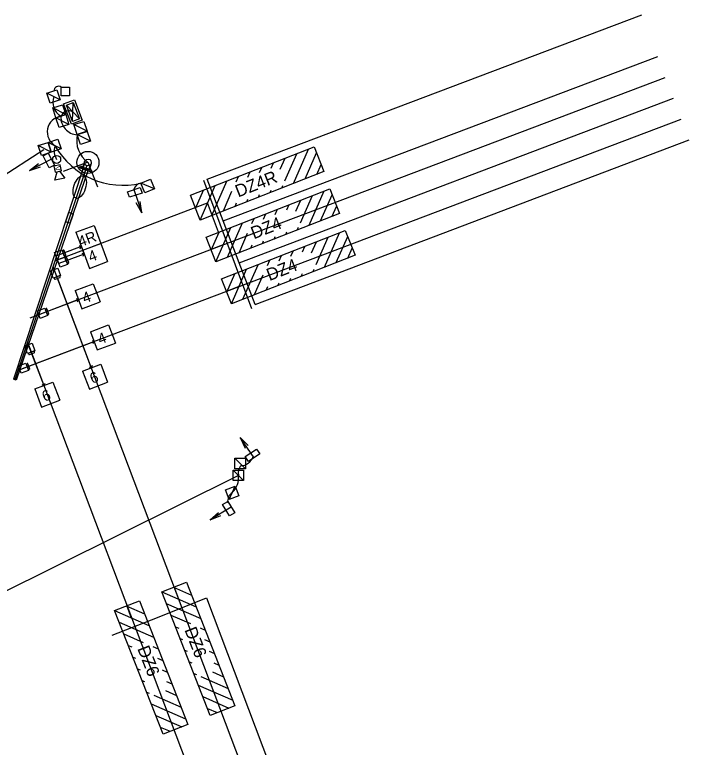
# Model space of a CAD drawing. Extents: x 510435 to 510719, y 1315254 to 1315553.
# Drawn here: x 510566.8 to 510719.1, y 1315365 to 1315530.6 of the extents above; entities that cross this region are included whole.
import ezdxf

# ---------------------------------------------------------------- set-up
doc = ezdxf.new("R2010")
doc.units = 0
for name, color, linetype in [('ContoursMinor_ep', 7, 'Continuous'), ('Default', 7, 'Continuous'), ('DTMTriangles_ep', 7, 'Continuous'), ('FloodLight_ep', 7, 'Continuous'), ('GroundShot_ep', 7, 'Continuous'), ('PilingColumn_ep', 7, 'Continuous'), ('PointLocator_ep', 7, 'Continuous'), ('ScratchEle_dp', 7, 'Continuous'), ('ShldrPaved_ep', 7, 'Continuous'), ('TextElevLabel', 7, 'Continuous'), ('TextPtLabel', 7, 'Continuous'), ('TextSurveyLabel', 7, 'Continuous'), ('TreeLineWoods_ep', 7, 'Continuous'), ('WaterEdge_ep', 7, 'Continuous')]:
    doc.layers.add(name, color=color, linetype=linetype)

# ---------------------------------------------------------------- blocks, each defined once
blk = doc.blocks.new('VSVideoCamera')
at = {"layer": 'TextElevLabel'}
blk.add_line((0, -0.59), (0, 0.59), dxfattribs=at)
blk.add_lwpolyline([(0, 1.41), (-2.81, 1.41), (-2.81, -1.41), (0, -1.41)], close=True, dxfattribs=at)
blk.add_lwpolyline([(0, 0.59), (3.52, 2.34), (3.52, -2.34), (0, -0.59)], dxfattribs=at)
blk.add_text('V', height=2.25, dxfattribs=at).set_placement((-2.41, -1.12))
blk = doc.blocks.new('SignalPoles_cel_SPoleConcN02')
at = {"layer": 'PilingColumn_ep'}
blk.add_lwpolyline([(-0.25, -0.25), (-0.25, 0.25), (0.25, 0.25), (0.25, -0.25)], close=True, dxfattribs=at)
blk = doc.blocks.new('MastArmD4')
at = {"layer": 'TextSurveyLabel'}
for p, q in [((0.25, 1.5), (0, 1.5)), ((0, 1.5), (0, -1.5)), ((0, -1.04), (0, 1.04)), ((0.25, 1.5), (0.25, -1.5)), ((0.25, 0.58), (11.7, 0.52)), ((9.7, 0.54), (46, 0.33)), ((9.7, 0.54), (9.7, -0.54)), ((11.7, 0.52), (11.7, -0.52)), ((46, 0.33), (46, -0.33)), ((0.25, -1.5), (0, -1.5)), ((0.25, -0.58), (11.7, -0.52)), ((9.7, -0.54), (46, -0.33))]:
    blk.add_line(p, q, dxfattribs=at)

msp = doc.modelspace()

# ---------------------------------------------------------------- linework, layer by layer
at = {"layer": 'ContoursMinor_ep'}
msp.add_circle((510583.29, 1315497.18), 2.5, dxfattribs=at)
msp.add_circle((510583.29, 1315497.18), 2.5, dxfattribs=at)
at = {"layer": 'Default'}
for p, q in [((510627.77, 1315493.02), (510630.46, 1315499.17)), ((510629.7, 1315492.43), (510633.1, 1315500.2)), ((510632.33, 1315493.46), (510634.9, 1315499.35)), ((510626.74, 1315495.66), (510627.83, 1315498.14)), ((510622.04, 1315494.89), (510622.56, 1315496.08)), ((510624.68, 1315495.92), (510625.2, 1315497.11)), ((510634.96, 1315494.49), (510635.94, 1315496.71)), ((510616.77, 1315492.82), (510617.29, 1315494.01)), ((510619.41, 1315493.86), (510619.93, 1315495.05)), ((510611.26, 1315485.21), (510614.66, 1315492.98)), ((510607.6, 1315486.81), (510609.39, 1315490.92)), ((510608.63, 1315484.18), (510612.03, 1315491.95)), ((510613.9, 1315486.24), (510615.83, 1315490.67)), ((510624.43, 1315490.36), (510624.69, 1315490.96)), ((510627.06, 1315491.4), (510627.33, 1315492)), ((510633.23, 1315482.98), (510636.62, 1315490.75)), ((510621.8, 1315489.33), (510622.06, 1315489.93)), ((510631.3, 1315483.57), (510633.99, 1315489.72)), ((510635.86, 1315484.01), (510638.43, 1315489.89)), ((510616.53, 1315487.27), (510616.86, 1315488.03)), ((510619.16, 1315488.3), (510619.43, 1315488.9)), ((510628.2, 1315486.47), (510628.72, 1315487.66)), ((510630.27, 1315486.2), (510631.36, 1315488.69)), ((510625.57, 1315485.43), (510626.09, 1315486.62)), ((510638.49, 1315485.04), (510639.46, 1315487.26)), ((510620.3, 1315483.37), (510620.82, 1315484.56)), ((510622.94, 1315484.4), (510623.46, 1315485.59)), ((510612.16, 1315474.72), (510615.56, 1315482.5)), ((510614.79, 1315475.75), (510618.19, 1315483.53)), ((510630.59, 1315481.94), (510630.85, 1315482.54)), ((510611.13, 1315477.36), (510612.92, 1315481.47)), ((510617.42, 1315476.79), (510619.36, 1315481.21)), ((510627.96, 1315480.91), (510628.22, 1315481.51)), ((510636.76, 1315473.52), (510640.15, 1315481.3)), ((510622.69, 1315478.85), (510622.95, 1315479.45)), ((510625.33, 1315479.88), (510625.59, 1315480.48)), ((510633.8, 1315476.75), (510634.89, 1315479.23)), ((510634.83, 1315474.12), (510637.52, 1315480.27)), ((510639.39, 1315474.55), (510641.96, 1315480.44)), ((510620.06, 1315477.82), (510620.39, 1315478.58)), ((510631.73, 1315477.01), (510632.25, 1315478.2)), ((510642.02, 1315475.59), (510642.99, 1315477.81)), ((510626.47, 1315474.95), (510626.99, 1315476.14)), ((510629.1, 1315475.98), (510629.62, 1315477.17)), ((510618.32, 1315466.3), (510621.72, 1315474.08)), ((510623.83, 1315473.92), (510624.35, 1315475.11)), ((510615.69, 1315465.27), (510619.08, 1315473.04)), ((510634.12, 1315472.49), (510634.38, 1315473.09)), ((510614.65, 1315467.9), (510616.45, 1315472.01)), ((510620.95, 1315467.33), (510622.89, 1315471.76)), ((510628.85, 1315470.43), (510629.12, 1315471.03)), ((510631.49, 1315471.46), (510631.75, 1315472.06)), ((510623.59, 1315468.36), (510623.92, 1315469.13)), ((510626.22, 1315469.4), (510626.48, 1315469.99)), ((510602.6, 1315401.21), (510606.71, 1315399.41)), ((510599.97, 1315400.18), (510607.74, 1315396.78)), ((510591.95, 1315396.98), (510596.06, 1315395.19)), ((510601, 1315397.55), (510608.78, 1315394.15)), ((510589.32, 1315395.95), (510597.09, 1315392.55)), ((510602.03, 1315394.91), (510606.46, 1315392.98)), ((510590.35, 1315393.32), (510598.13, 1315389.92)), ((510603.06, 1315392.28), (510603.83, 1315391.94)), ((510608.62, 1315392.03), (510609.81, 1315391.51)), ((510591.38, 1315390.68), (510595.81, 1315388.75)), ((510604.1, 1315389.64), (510604.69, 1315389.38)), ((510592.41, 1315388.05), (510593.18, 1315387.72)), ((510609.65, 1315389.4), (510610.84, 1315388.88)), ((510597.97, 1315387.81), (510599.16, 1315387.29)), ((510605.13, 1315387.01), (510605.73, 1315386.75)), ((510610.68, 1315386.77), (510611.87, 1315386.25)), ((510593.45, 1315385.42), (510594.05, 1315385.16)), ((510599, 1315385.17), (510600.19, 1315384.65)), ((510606.16, 1315384.38), (510606.76, 1315384.12)), ((510611.71, 1315384.13), (510612.9, 1315383.61)), ((510594.48, 1315382.78), (510595.08, 1315382.52)), ((510600.03, 1315382.54), (510601.22, 1315382.02)), ((510607.19, 1315381.74), (510607.79, 1315381.48)), ((510611.45, 1315382.07), (510613.93, 1315380.98)), ((510595.51, 1315380.15), (510596.11, 1315379.89)), ((510601.06, 1315379.91), (510602.25, 1315379.39)), ((510608.82, 1315381.03), (510614.97, 1315378.35)), ((510608.22, 1315379.11), (510616, 1315375.71)), ((510596.54, 1315377.52), (510597.14, 1315377.25)), ((510598.17, 1315376.81), (510604.32, 1315374.12)), ((510600.8, 1315377.84), (510603.28, 1315376.75)), ((510609.25, 1315376.48), (510615.14, 1315373.9)), ((510597.57, 1315374.88), (510605.35, 1315371.48)), ((510610.29, 1315373.84), (510612.51, 1315372.87)), ((510598.6, 1315372.25), (510604.49, 1315369.68)), ((510599.64, 1315369.62), (510601.86, 1315368.65))]:
    msp.add_line(p, q, dxfattribs=at)
for points in [[(510606.44, 1315489.76), (510634.37, 1315500.7), (510636.56, 1315495.12), (510608.63, 1315484.18)], [(510609.97, 1315480.31), (510637.9, 1315491.25), (510640.09, 1315485.66), (510612.16, 1315474.72)], [(510613.5, 1315470.86), (510641.43, 1315481.8), (510643.62, 1315476.21), (510615.69, 1315465.27)], [(510605.56, 1315402.37), (510616.5, 1315374.44), (510610.91, 1315372.25), (510599.97, 1315400.18)], [(510594.91, 1315398.14), (510605.85, 1315370.21), (510600.26, 1315368.02), (510589.32, 1315395.95)]]:
    msp.add_lwpolyline(points, close=True, dxfattribs=at)
for centre, radius, start, end in [((510576.63, 1315513.42), 0.972, 50.2933, 185.4121), ((510579, 1315510.77), 3.62, 158.7146, 240.5192), ((510578.97, 1315506.96), 1.87, 59.8376, 159.3625), ((510577.7, 1315504.08), 3.58, 97.6287, 240.6576), ((510581.03, 1315507.29), 3.83, 174.9872, 267.9077), ((510586.92, 1315502.17), 6.17, 167.7927, 233.925), ((510579.06, 1315499.75), 3.4, 160.1632, 213.8023), ((510591.19, 1315509.67), 17.63, 209.8745, 283.3302), ((510595.54, 1315490.65), 1.89, 98.6133, 168.1351), ((510617.61, 1315431.85), 3.22, 272.8933, 339.7985), ((510620.03, 1315426.99), 2.79, 143.811, 188.8839), ((510612.82, 1315425.91), 4.52, 314.3812, 6.8204), ((510617.29, 1315420.59), 2.45, 123.9662, 187.1662)]:
    msp.add_arc(centre, radius, start, end, dxfattribs=at)
at = {"layer": 'DTMTriangles_ep'}
msp.add_circle((510576.24, 1315497.86), 0.9, dxfattribs=at)
at = {"layer": 'FloodLight_ep'}
for q in [(510577.71, 1315495.11), (510585.47, 1315491.67)]:
    msp.add_line((510583.31, 1315497.27), q, dxfattribs=at)
at = {"layer": 'GroundShot_ep'}
for p, q in [((510574.04, 1315512.85), (510576.27, 1315513.58)), ((510574.77, 1315510.62), (510574.04, 1315512.85)), ((510577, 1315511.35), (510574.04, 1315512.85)), ((510576.27, 1315513.58), (510577, 1315511.35)), ((510577, 1315511.35), (510574.77, 1315510.62)), ((510575.34, 1315509.5), (510577.57, 1315510.23)), ((510576.07, 1315507.27), (510575.34, 1315509.5)), ((510578.29, 1315508), (510575.34, 1315509.5)), ((510577.57, 1315510.23), (510578.29, 1315508)), ((510576.07, 1315507.27), (510578.29, 1315508)), ((510578.29, 1315508), (510576.07, 1315507.27)), ((510576.79, 1315505.05), (510576.07, 1315507.27)), ((510579.02, 1315505.77), (510576.07, 1315507.27)), ((510578.29, 1315508), (510579.02, 1315505.77)), ((510579.02, 1315505.77), (510576.79, 1315505.05)), ((510580.15, 1315505.73), (510582.38, 1315506.46)), ((510580.88, 1315503.5), (510580.15, 1315505.73)), ((510583.11, 1315504.23), (510580.15, 1315505.73)), ((510582.38, 1315506.46), (510583.11, 1315504.23)), ((510583.11, 1315504.23), (510580.88, 1315503.5)), ((510580.89, 1315503.47), (510583.12, 1315504.2)), ((510583.12, 1315504.2), (510583.85, 1315501.97)), ((510574.31, 1315501.73), (510576.53, 1315502.46)), ((510576.53, 1315502.46), (510577.26, 1315500.23)), ((510581.62, 1315501.24), (510580.89, 1315503.47)), ((510583.85, 1315501.97), (510580.89, 1315503.47)), ((510572.08, 1315501), (510574.31, 1315501.73)), ((510572.8, 1315498.78), (510572.08, 1315501)), ((510575.03, 1315499.5), (510572.08, 1315501)), ((510574.31, 1315501.73), (510575.03, 1315499.5)), ((510575.03, 1315499.5), (510574.31, 1315501.73)), ((510577.26, 1315500.23), (510574.31, 1315501.73)), ((510583.85, 1315501.97), (510581.62, 1315501.24)), ((510575.03, 1315499.5), (510572.8, 1315498.78)), ((510577.26, 1315500.23), (510575.03, 1315499.5)), ((510595.26, 1315492.51), (510597.43, 1315493.38)), ((510596.12, 1315490.34), (510595.26, 1315492.51)), ((510598.3, 1315491.2), (510595.26, 1315492.51)), ((510597.43, 1315493.38), (510598.3, 1315491.2)), ((510598.3, 1315491.2), (510596.12, 1315490.34)), ((510616.51, 1315427.99), (510616.51, 1315430.34)), ((510616.51, 1315430.34), (510618.86, 1315430.34)), ((510618.86, 1315427.99), (510616.51, 1315430.34)), ((510618.86, 1315430.34), (510618.86, 1315427.99)), ((510618.86, 1315427.99), (510616.51, 1315427.99)), ((510616.08, 1315425.33), (510616.08, 1315427.67)), ((510616.08, 1315427.67), (510618.42, 1315427.67)), ((510618.42, 1315425.33), (510616.08, 1315427.67)), ((510618.42, 1315427.67), (510618.42, 1315425.33)), ((510618.42, 1315425.33), (510616.08, 1315425.33)), ((510614.36, 1315423.2), (510616.56, 1315424.02)), ((510615.18, 1315421), (510614.36, 1315423.2)), ((510615.18, 1315421), (510616.56, 1315424.02)), ((510616.56, 1315424.02), (510617.38, 1315421.83)), ((510617.38, 1315421.83), (510615.18, 1315421))]:
    msp.add_line(p, q, dxfattribs=at)
at = {"layer": 'PointLocator_ep'}
msp.add_line((510620.35, 1315464.12), (510609.49, 1315493.11), dxfattribs=at)
at = {"layer": 'ScratchEle_dp'}
for p, q in [((510577.8, 1315510.41), (510580.25, 1315511.35)), ((510578.43, 1315510.13), (510579.97, 1315510.71)), ((510579.85, 1315506.45), (510579.97, 1315510.71)), ((510579.97, 1315510.71), (510581.38, 1315507.04)), ((510580.25, 1315511.35), (510582.01, 1315506.76)), ((510579.56, 1315505.81), (510577.8, 1315510.41)), ((510578.43, 1315510.13), (510581.38, 1315507.04)), ((510579.85, 1315506.45), (510578.43, 1315510.13)), ((510582.01, 1315506.76), (510579.56, 1315505.81)), ((510581.38, 1315507.04), (510579.85, 1315506.45))]:
    msp.add_line(p, q, dxfattribs=at)
at = {"layer": 'ShldrPaved_ep'}
msp.add_line((510583.05, 1315496.47), (510582.27, 1315494.12), dxfattribs=at)
msp.add_ellipse((510581.44, 1315491.62), major_axis=(-0.83, -2.51), ratio=0.5, dxfattribs=at)
at = {"layer": 'TextElevLabel'}
for p, q in [((510581.8, 1315478.17), (510576.08, 1315476.01)), ((510582.43, 1315476.5), (510576.72, 1315474.33)), ((510581.16, 1315466.19), (510572.21, 1315462.79))]:
    msp.add_line(p, q, dxfattribs=at)
at = {"layer": 'TextPtLabel'}
for p, q in [((510521.96, 1315467.05), (510573.34, 1315500.1)), ((510553, 1315394.55), (510617.23, 1315426.44))]:
    msp.add_line(p, q, dxfattribs=at)
at = {"layer": 'TextSurveyLabel'}
for p, q in [((510582.54, 1315497.44), (510582.12, 1315496.19)), ((510582.58, 1315497.42), (510582.16, 1315496.18)), ((510582.54, 1315497.44), (510582.58, 1315497.42)), ((510581.72, 1315496.32), (510581.67, 1315496.18)), ((510583.97, 1315495.41), (510581.67, 1315496.18)), ((510582.24, 1315496.15), (510581.72, 1315496.32)), ((510582.55, 1315497.07), (510582.21, 1315496.08)), ((510583.48, 1315495.66), (510582.21, 1315496.08)), ((510583.81, 1315496.64), (510583.48, 1315495.66)), ((510584.01, 1315495.55), (510583.5, 1315495.73)), ((510584, 1315496.94), (510583.58, 1315495.7)), ((510584.04, 1315496.93), (510583.62, 1315495.69)), ((510584.04, 1315496.93), (510584, 1315496.94)), ((510584.01, 1315495.55), (510583.97, 1315495.41)), ((510581.32, 1315478.39), (510581.8, 1315478.17)), ((510581.58, 1315477.69), (510581.8, 1315478.17)), ((510577.96, 1315476.09), (510577.55, 1315477.19)), ((510578.31, 1315476.22), (510577.9, 1315477.32)), ((510578.31, 1315476.22), (510577.9, 1315477.32)), ((510581.94, 1315476.72), (510582.43, 1315476.5)), ((510582.21, 1315476.01), (510582.43, 1315476.5)), ((510578.59, 1315474.42), (510578.18, 1315475.52)), ((510578.95, 1315474.55), (510578.53, 1315475.65)), ((510578.95, 1315474.55), (510578.53, 1315475.65)), ((510575.88, 1315470.78), (510576.97, 1315471.2)), ((510576.43, 1315470.99), (510584.06, 1315450.8)), ((510580.67, 1315466.41), (510581.16, 1315466.19)), ((510580.94, 1315465.7), (510581.16, 1315466.19)), ((510574.44, 1315463.01), (510574.03, 1315464.11)), ((510567.99, 1315450.4), (510584.71, 1315456.74)), ((510569.84, 1315456), (510573.37, 1315446.78)), ((510584.22, 1315456.96), (510584.71, 1315456.74)), ((510584.49, 1315456.25), (510584.71, 1315456.74)), ((510570.07, 1315453.77), (510571.16, 1315454.19)), ((510570.15, 1315450.59), (510569.73, 1315451.69)), ((510583.57, 1315451.01), (510584.06, 1315450.8)), ((510584.27, 1315451.29), (510584.06, 1315450.8)), ((510572.88, 1315447), (510573.37, 1315446.78)), ((510573.59, 1315447.27), (510573.37, 1315446.78))]:
    msp.add_line(p, q, dxfattribs=at)
for points in [[(510583.24, 1315496.41), (510582.86, 1315496.54), (510582.59, 1315496.84), (510582.51, 1315497.23), (510582.64, 1315497.61), (510582.94, 1315497.88), (510583.34, 1315497.96), (510583.72, 1315497.83), (510583.98, 1315497.53), (510584.06, 1315497.14), (510583.93, 1315496.75), (510583.63, 1315496.49)], [(510577.44, 1315477.48), (510578.07, 1315475.8), (510576.4, 1315475.17), (510575.77, 1315476.84)], [(510578.07, 1315475.8), (510578.7, 1315474.13), (510577.03, 1315473.5), (510576.4, 1315475.17)], [(510577.13, 1315471.66), (510575.46, 1315471.03), (510574.83, 1315472.7), (510576.5, 1315473.33)], [(510573.57, 1315464.26), (510574.2, 1315462.59), (510572.53, 1315461.96), (510571.89, 1315463.63)], [(510571.32, 1315454.65), (510569.65, 1315454.01), (510569.01, 1315455.68), (510570.68, 1315456.32)], [(510569.27, 1315451.85), (510569.91, 1315450.17), (510568.24, 1315449.54), (510567.6, 1315451.21)]]:
    msp.add_lwpolyline(points, close=True, dxfattribs=at)
for points in [[(510577.55, 1315477.19), (510577.96, 1315476.09)], [(510578.18, 1315475.52), (510578.59, 1315474.42)], [(510576.84, 1315471.55), (510575.74, 1315471.14)], [(510573.67, 1315463.97), (510574.09, 1315462.88)], [(510571.03, 1315454.54), (510569.93, 1315454.12)], [(510569.38, 1315451.56), (510569.8, 1315450.46)]]:
    msp.add_lwpolyline(points, dxfattribs=at)
for centre, radius, start, end in [((510577.79, 1315477.28), 0.115, 20.7534, 140.0731), ((510576.06, 1315478.73), 2.14, 313.9699, 320.0732), ((510577.87, 1315473.95), 2.14, 81.4335, 87.5368), ((510577.87, 1315473.95), 2.14, 81.4335, 87.5368), ((510578.21, 1315476.18), 0.115, 261.4335, 20.7534), ((510578.21, 1315476.18), 0.115, 261.4335, 20.7534), ((510578.42, 1315475.61), 0.115, 20.7534, 140.0731), ((510576.69, 1315477.06), 2.14, 313.9699, 320.0732), ((510578.5, 1315472.28), 2.14, 81.4335, 87.5368), ((510578.5, 1315472.28), 2.14, 81.4335, 87.5368), ((510578.84, 1315474.51), 0.115, 261.4335, 20.7534), ((510578.84, 1315474.51), 0.115, 261.4335, 20.7534), ((510573.6, 1315471.23), 2.14, 351.3341, 357.4374), ((510575.84, 1315470.89), 0.115, 171.3341, 290.6539), ((510578.39, 1315473.03), 2.14, 223.8705, 229.9738), ((510576.93, 1315471.3), 0.115, 290.654, 49.9737), ((510572.19, 1315465.52), 2.14, 313.9699, 320.0732), ((510573.92, 1315464.07), 0.115, 20.7534, 140.0731), ((510574, 1315460.74), 2.14, 81.4335, 87.5368), ((510574.33, 1315462.97), 0.115, 261.4335, 20.7534), ((510572.57, 1315456.03), 2.14, 224.1322, 230.2354), ((510571.12, 1315454.3), 0.115, 290.9156, 50.2354), ((510567.79, 1315454.21), 2.14, 351.5958, 357.699), ((510570.03, 1315453.88), 0.115, 171.5958, 290.9156), ((510567.89, 1315453.1), 2.14, 313.9699, 320.0732), ((510569.63, 1315451.65), 0.115, 20.7534, 140.0731), ((510569.71, 1315448.32), 2.14, 81.4335, 87.5368), ((510570.04, 1315450.55), 0.115, 261.4335, 20.7534)]:
    msp.add_arc(centre, radius, start, end, dxfattribs=at)
at = {"layer": 'TreeLineWoods_ep'}
for p, q in [((510610.22, 1315493.38), (510708.4, 1315530.58)), ((510613.83, 1315483.96), (510711.97, 1315521.15)), ((510570.25, 1315462.05), (510713.7, 1315516.41)), ((510617.44, 1315474.54), (510715.55, 1315511.71)), ((510567.51, 1315450.22), (510717.31, 1315506.99)), ((510621.06, 1315465.12), (510719.12, 1315502.28)), ((510582.72, 1315495.48), (510566.79, 1315448.09)), ((510613.83, 1315483.96), (510610.22, 1315493.38)), ((510575.82, 1315474.95), (510610.34, 1315488.03)), ((510612.81, 1315481.41), (510610.34, 1315488.03)), ((510617.44, 1315474.54), (510613.83, 1315483.96)), ((510581.8, 1315478.17), (510582.43, 1315476.5)), ((510613.87, 1315478.58), (510611.06, 1315477.52)), ((510621.06, 1315465.12), (510617.44, 1315474.54)), ((510575.4, 1315473.7), (510656.98, 1315257.75)), ((510617.4, 1315469.13), (510614.59, 1315468.06)), ((510580.4, 1315468.22), (510581.94, 1315464.13)), ((510569.84, 1315456), (510569.33, 1315454.85)), ((510569.64, 1315456.55), (510646.33, 1315253.52)), ((510603.82, 1315398.47), (510602.76, 1315401.27)), ((510599, 1315394.4), (510610.06, 1315398.79)), ((510610.06, 1315398.79), (510662.51, 1315259.95)), ((510593.17, 1315394.24), (510592.11, 1315397.05)), ((510588.76, 1315390.34), (510599, 1315394.4))]:
    msp.add_line(p, q, dxfattribs=at)
at = {"layer": 'WaterEdge_ep'}
for p, q in [((510573.16, 1315498.7), (510574.35, 1315499.31)), ((510574.35, 1315499.31), (510575.75, 1315496.61)), ((510575.05, 1315497.96), (510570.1, 1315495.4)), ((510574.56, 1315495.99), (510573.16, 1315498.7)), ((510570.1, 1315495.4), (510572.15, 1315496.96)), ((510570.1, 1315495.4), (510572.62, 1315496.19)), ((510575.75, 1315496.61), (510574.56, 1315495.99)), ((510592.23, 1315490.58), (510595.12, 1315491.55)), ((510593.67, 1315491.07), (510595.46, 1315485.79)), ((510595.12, 1315491.55), (510595.55, 1315490.28)), ((510592.66, 1315489.31), (510592.23, 1315490.58)), ((510595.55, 1315490.28), (510592.66, 1315489.31)), ((510595.46, 1315485.79), (510594.22, 1315488.04)), ((510595.46, 1315485.79), (510595.06, 1315488.4)), ((510580.58, 1315481.43), (510584.68, 1315482.97)), ((510584.68, 1315482.97), (510586.21, 1315478.88)), ((510580.58, 1315481.43), (510582.12, 1315477.34)), ((510582.12, 1315477.34), (510586.21, 1315478.88)), ((510582.12, 1315477.34), (510586.21, 1315478.88)), ((510586.21, 1315478.88), (510587.75, 1315474.78)), ((510582.12, 1315477.34), (510583.66, 1315473.24)), ((510583.66, 1315473.24), (510587.75, 1315474.78)), ((510580.4, 1315468.22), (510584.49, 1315469.76)), ((510584.49, 1315469.76), (510586.03, 1315465.67)), ((510580.4, 1315468.22), (510581.94, 1315464.13)), ((510581.94, 1315464.13), (510586.03, 1315465.67)), ((510583.88, 1315458.94), (510587.98, 1315460.48)), ((510587.98, 1315460.48), (510589.52, 1315456.38)), ((510583.88, 1315458.94), (510585.42, 1315454.85)), ((510585.42, 1315454.85), (510589.52, 1315456.38)), ((510582.11, 1315450.06), (510586.2, 1315451.6)), ((510586.2, 1315451.6), (510587.74, 1315447.51)), ((510582.11, 1315450.06), (510583.65, 1315445.97)), ((510571.31, 1315446.01), (510575.41, 1315447.55)), ((510571.31, 1315446.01), (510572.85, 1315441.91)), ((510575.41, 1315447.55), (510576.94, 1315443.45)), ((510583.65, 1315445.97), (510587.74, 1315447.51)), ((510572.85, 1315441.91), (510576.94, 1315443.45)), ((510617.69, 1315435.06), (510619.49, 1315433.22)), ((510620.84, 1315430.46), (510617.69, 1315435.06)), ((510617.69, 1315435.06), (510618.78, 1315432.65)), ((510618.83, 1315430.71), (510621.34, 1315432.43)), ((510622.1, 1315431.33), (510619.59, 1315429.6)), ((510621.34, 1315432.43), (510622.1, 1315431.33)), ((510619.59, 1315429.6), (510618.83, 1315430.71)), ((510613.72, 1315419.92), (510614.86, 1315420.61)), ((510615.3, 1315417.31), (510613.72, 1315419.92)), ((510614.86, 1315420.61), (510616.45, 1315418.01)), ((510615.65, 1315419.31), (510610.89, 1315416.41)), ((510610.89, 1315416.41), (510612.82, 1315418.11)), ((510616.45, 1315418.01), (510615.3, 1315417.31)), ((510610.89, 1315416.41), (510613.35, 1315417.38))]:
    msp.add_line(p, q, dxfattribs=at)

# ---------------------------------------------------------------- block references
at = {"layer": 'PilingColumn_ep', "xscale": 3.843400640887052, "yscale": 3.843400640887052, "rotation": 1.131536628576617e-07}
msp.add_blockref('SignalPoles_cel_SPoleConcN02', (510578.21, 1315513.21), dxfattribs=at)
at = {"layer": 'TextSurveyLabel'}
for name, p, xscale, yscale, rotation in [('MastArmD4', (510582.8, 1315495.74), 1.0928961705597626, 0.9999999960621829, -108.57724603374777), ('VSVideoCamera', (510576.61, 1315495.14), 0.49999999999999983, 0.4999999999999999, -78.0007281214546)]:
    msp.add_blockref(name, p, dxfattribs=dict(at, xscale=xscale, yscale=yscale, rotation=rotation))

# ---------------------------------------------------------------- texts
at = {"layer": 'Default'}
for s, rotation, p in [('DZ4R', 21.3911, (510617.23, 1315489.26)), ('DZ4 ', 21.3911, (510620.76, 1315479.81)), ('DZ4 ', 21.3911, (510624.29, 1315470.36)), ('DZ6 ', 291.3911, (510605.06, 1315391.58)), ('DZ6 ', 291.3911, (510594.41, 1315387.35))]:
    msp.add_text(s, height=2.8, rotation=rotation, dxfattribs=at).set_placement(p)
at = {"layer": 'WaterEdge_ep'}
for s, p in [('4R', (510581.62, 1315478.07)), ('4', (510583.91, 1315474.66)), ('4', (510582.56, 1315465.31)), ('4', (510586.05, 1315456.03)), ('6', (510584.27, 1315447.15)), ('6', (510573.47, 1315443.1))]:
    msp.add_text(s, height=2.4, rotation=20.582, dxfattribs=at).set_placement(p)

doc.saveas('drawing.dxf')
